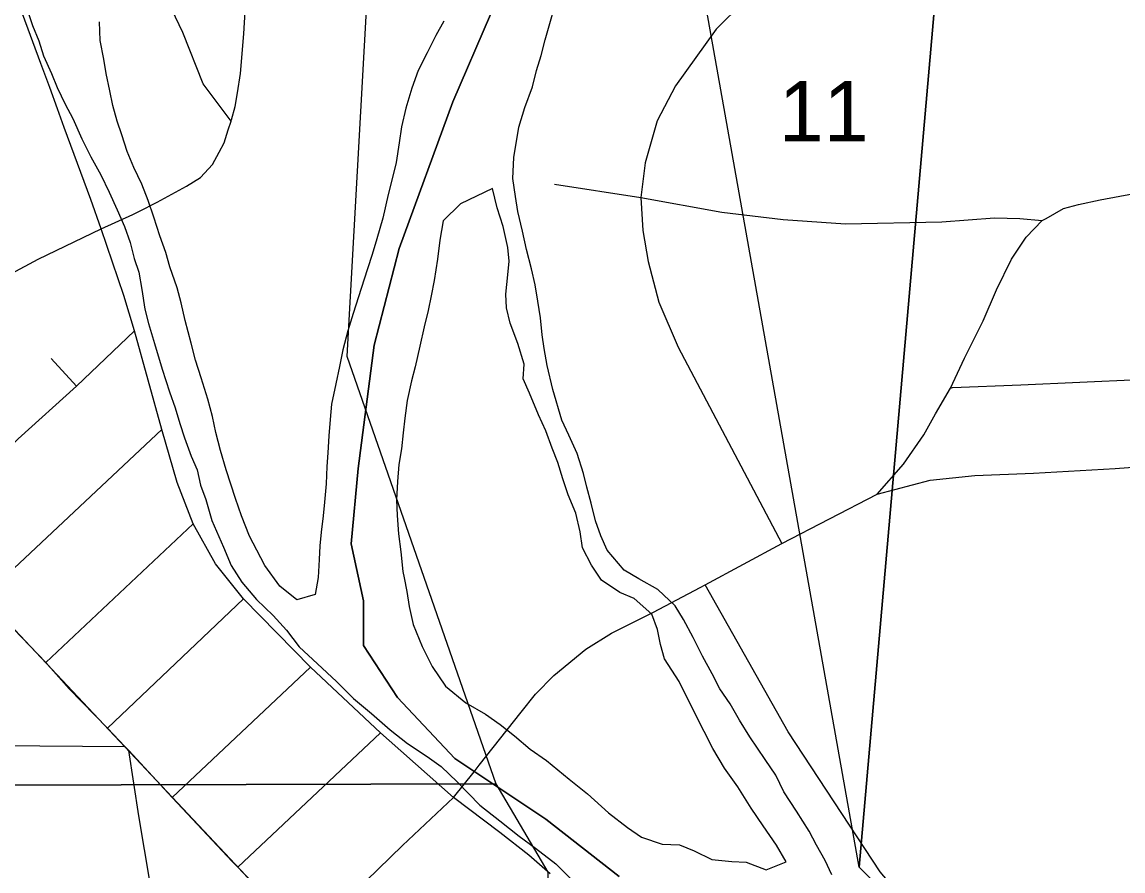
# Model space of a CAD drawing. Extents: x 0 to 34, y 0 to 22.
# Drawn here: x 5.661 to 6.424, y 19.444 to 20.032 of the extents above; entities that cross this region are included whole.
import ezdxf

# ---------------------------------------------------------------- set-up
doc = ezdxf.new("R2010")
doc.units = 0
for name, color, linetype in [('GM_X_City_Street', 7, 'Continuous'), ('GM_X_County_Road', 7, 'Continuous'), ('GM_X_Major_River', 7, 'Continuous'), ('GM_X_Rail_Line', 7, 'Continuous'), ('GM_X_Section', 7, 'Continuous'), ('GM_X_Section_Text', 7, 'Continuous'), ('GM_X_State_Route', 7, 'Continuous'), ('GM_X_Township_Road', 7, 'Continuous')]:
    doc.layers.add(name, color=color, linetype=linetype)

msp = doc.modelspace()

# ---------------------------------------------------------------- linework, layer by layer
at = {"layer": 'GM_X_City_Street'}
for p, q in [((5.69908, 19.77954), (5.68137, 19.79885)), ((5.63415, 19.63335), (5.75809, 19.7495)), ((5.67771, 19.58808), (5.77993, 19.68429)), ((5.72049, 19.54272), (5.81472, 19.63218)), ((5.76529, 19.49469), (5.86126, 19.58503)), ((5.81082, 19.44626), (5.9096, 19.5394)), ((5.61432, 19.53093), (5.73258, 19.52994))]:
    msp.add_line(p, q, dxfattribs=at)
for points in [[(5.80628, 19.96327), (5.7868, 19.98904), (5.77257, 20.0246), (5.76261, 20.04594), (5.75692, 20.10143), (5.74554, 20.16545), (5.73985, 20.20102), (5.73416, 20.24654), (5.72705, 20.2878), (5.71851, 20.31625), (5.71424, 20.33759), (5.71282, 20.36462), (5.70855, 20.3945), (5.70589, 20.45235), (5.70855, 20.49754), (5.71096, 20.56277), (5.70911, 20.59297), (5.70541, 20.65399), (5.70082, 20.69532), (5.69167, 20.73859), (5.659, 20.86529), (5.65113, 20.89381), (5.64998, 20.9)], [(6.48949, 20.17565), (6.41974, 20.16506), (6.34311, 20.1509), (6.31729, 20.1434), (6.2798, 20.12841), (6.24316, 20.10925), (6.21817, 20.09426), (6.18652, 20.07011), (6.16153, 20.04595), (6.14238, 20.02679), (6.11405, 19.98764), (6.10156, 19.96349), (6.09323, 19.93434), (6.09013, 19.9103), (6.0916, 19.88736), (6.09531, 19.86589), (6.10271, 19.83776), (6.11603, 19.80667), (6.18784, 19.67065)], [(6.03036, 19.91953), (6.09013, 19.9103), (6.14638, 19.90019), (6.18877, 19.89499), (6.23192, 19.89201), (6.29885, 19.8935), (6.33529, 19.8961), (6.35277, 19.89573), (6.36839, 19.89424)], [(6.36839, 19.89424), (6.37099, 19.89572), (6.38316, 19.90263), (6.39345, 19.90539), (6.40852, 19.90865), (6.44191, 19.91493), (6.48534, 19.92372)], [(6.25386, 19.70479), (6.27219, 19.72563), (6.28625, 19.74596), (6.29428, 19.76053), (6.30483, 19.7781), (6.31437, 19.79894), (6.32743, 19.8248), (6.33672, 19.84639), (6.34701, 19.86748), (6.3573, 19.88279), (6.36839, 19.89424)], [(6.30483, 19.7781), (6.30607, 19.77873), (6.35351, 19.78041), (6.43536, 19.78418), (6.45131, 19.7867), (6.46223, 19.78964), (6.49539, 19.81021), (6.52205, 19.82757), (6.55206, 19.84886), (6.55666, 19.85203), (6.56012, 19.85347), (6.56386, 19.85462), (6.56905, 19.85434), (6.62982, 19.84818)], [(5.59105, 19.67895), (5.65852, 19.74307), (5.69908, 19.77954), (5.73926, 19.81788)], [(6.13129, 19.64007), (6.13478, 19.64191), (6.18784, 19.67065), (6.25386, 19.70479), (6.29077, 19.71458), (6.32165, 19.71759), (6.36232, 19.71935), (6.41899, 19.72261), (6.47135, 19.72658), (6.5006, 19.732), (6.53022, 19.74175), (6.56901, 19.75773)], [(5.96036, 19.49467), (5.97456, 19.51243), (5.97817, 19.51696), (6.00714, 19.55378), (6.0172, 19.56613), (6.02983, 19.57906), (6.05208, 19.59741), (6.06983, 19.60853), (6.09899, 19.62296), (6.13129, 19.64007)], [(6.43618, 19.23919), (6.37806, 19.30501), (6.29517, 19.3971), (6.25603, 19.44315), (6.19214, 19.54014), (6.13478, 19.64191)], [(5.8027, 19.10411), (5.79262, 19.16742), (5.78376, 19.22821), (5.76781, 19.32468), (5.76345, 19.35451), (5.75786, 19.38657), (5.75002, 19.43534), (5.74218, 19.48194), (5.73519, 19.52725)], [(5.8573, 19.39686), (5.89119, 19.4287), (5.92487, 19.46147), (5.96036, 19.49467)]]:
    msp.add_lwpolyline(points, dxfattribs=at)
at = {"layer": 'GM_X_County_Road'}
msp.add_line((5.96036, 19.49467), (5.91558, 19.53414), dxfattribs=at)
for points in [[(5.68583, 19.97163), (5.68052, 19.98641), (5.67435, 20.00313), (5.66155, 20.03747), (5.65481, 20.05838)], [(5.716, 19.88847), (5.70884, 19.909), (5.69047, 19.9587), (5.68583, 19.97163)], [(5.91558, 19.53414), (5.9096, 19.5394), (5.86126, 19.58503), (5.81472, 19.63218), (5.79529, 19.65642), (5.77993, 19.68429), (5.76872, 19.71285), (5.75809, 19.7495), (5.73926, 19.81788), (5.73189, 19.8424), (5.716, 19.88847)], [(6.02723, 19.44165), (6.01247, 19.45461), (5.99244, 19.47027), (5.96036, 19.49467)]]:
    msp.add_lwpolyline(points, dxfattribs=at)
at = {"layer": 'GM_X_Major_River'}
for points in [[(5.66388, 20.04321), (5.66855, 20.02943), (5.67289, 20.01871), (5.67611, 20.00838), (5.68157, 19.99611), (5.68556, 19.98653), (5.69103, 19.97502), (5.69653, 19.96503), (5.70271, 19.95084), (5.70892, 19.93856), (5.71589, 19.92588), (5.72173, 19.91398), (5.72719, 19.90171), (5.73228, 19.89021), (5.73624, 19.8791), (5.73906, 19.86803), (5.74229, 19.85846), (5.74434, 19.84664), (5.74635, 19.83292), (5.74881, 19.823), (5.7531, 19.80923), (5.75844, 19.79126), (5.76345, 19.77558), (5.76741, 19.76448), (5.77062, 19.75378), (5.77384, 19.74383), (5.77853, 19.7312), (5.78252, 19.72162), (5.78497, 19.71093), (5.78857, 19.70098), (5.79284, 19.68645), (5.80084, 19.66805), (5.80629, 19.6554), (5.81366, 19.64385), (5.82368, 19.63187), (5.83523, 19.62062), (5.84453, 19.61055), (5.85342, 19.59897), (5.8661, 19.58731), (5.87916, 19.57489), (5.89108, 19.56324), (5.90341, 19.55273), (5.91649, 19.54145), (5.92846, 19.53208), (5.94196, 19.52307), (5.9517, 19.51603)], [(5.87476, 19.7566), (5.87378, 19.74521), (5.87317, 19.73345), (5.8726, 19.72396), (5.87198, 19.71182), (5.87097, 19.6993), (5.87003, 19.68982), (5.86866, 19.67845), (5.86772, 19.66897), (5.86715, 19.65948), (5.86652, 19.64696), (5.86439, 19.63522), (5.85179, 19.63168), (5.83982, 19.64104), (5.82946, 19.65531), (5.82397, 19.66606), (5.81884, 19.67566), (5.81342, 19.68983), (5.8091, 19.7017), (5.80588, 19.71164), (5.80265, 19.72159), (5.79874, 19.73497), (5.79557, 19.74757), (5.79313, 19.75864), (5.78994, 19.77048), (5.7853, 19.78539), (5.78136, 19.79764), (5.77855, 19.80947), (5.7743, 19.82514), (5.77151, 19.83735), (5.76867, 19.84767), (5.76364, 19.86221), (5.7608, 19.87215), (5.75684, 19.88363), (5.75254, 19.89663), (5.74859, 19.90811), (5.74426, 19.9196), (5.73879, 19.93111), (5.73407, 19.94223), (5.7305, 19.9537), (5.72727, 19.96326), (5.72406, 19.97397), (5.72198, 19.98427), (5.71955, 19.9961), (5.71785, 20.00601), (5.71545, 20.01898), (5.71494, 20.03191)], [(5.95352, 20.03237), (5.94801, 20.0226), (5.94207, 20.01057), (5.93575, 19.99816), (5.93133, 19.98609), (5.92726, 19.97211), (5.92435, 19.95925), (5.92261, 19.94826), (5.92044, 19.93463), (5.91796, 19.92404), (5.91506, 19.91232), (5.91132, 19.89606), (5.90724, 19.8817), (5.90399, 19.87075), (5.90075, 19.86094), (5.89631, 19.84735), (5.89065, 19.82999), (5.88699, 19.8179), (5.88369, 19.80467), (5.88119, 19.79332), (5.87867, 19.78121), (5.87573, 19.76721), (5.87476, 19.7566)], [(6.18369, 19.51014), (6.17631, 19.52093), (6.1656, 19.53673), (6.15861, 19.54827), (6.15199, 19.55942), (6.14498, 19.56983), (6.13949, 19.5802), (6.13289, 19.59249), (6.12631, 19.60555), (6.11971, 19.61784), (6.11383, 19.62746), (6.10189, 19.63872), (6.08874, 19.64621), (6.0786, 19.65212), (6.06672, 19.66604), (6.06236, 19.67601), (6.05876, 19.68634), (6.05559, 19.69857), (6.05277, 19.70964), (6.05029, 19.71919), (6.04601, 19.73296), (6.04018, 19.74562), (6.03544, 19.75597), (6.02903, 19.77738), (6.02517, 19.7938), (6.02313, 19.80562), (6.02179, 19.81515), (6.02051, 19.82695), (6.01883, 19.83839), (6.01678, 19.84983), (6.01434, 19.8609), (6.01081, 19.87427), (6.00802, 19.88686), (6.00487, 19.90061), (6.00317, 19.9109), (6.00152, 19.92348), (6.00218, 19.9379), (6.00564, 19.95911), (6.00971, 19.97271), (6.01493, 19.98704), (6.01781, 19.99838), (6.02105, 20.00857), (6.02393, 20.01953), (6.02884, 20.03729)], [(5.98733, 19.91655), (5.96508, 19.90598), (5.95307, 19.89407), (5.95091, 19.88081), (5.94913, 19.86755), (5.94694, 19.85277), (5.94483, 19.84218), (5.94273, 19.83196), (5.93985, 19.82062), (5.93693, 19.80738), (5.9336, 19.79301), (5.93113, 19.78318), (5.9282, 19.76956), (5.92645, 19.75744), (5.92548, 19.7472), (5.92413, 19.73621), (5.92239, 19.72523), (5.9214, 19.71347), (5.92077, 19.70094), (5.92131, 19.68991), (5.92221, 19.67735), (5.92386, 19.66478), (5.92511, 19.65108), (5.92616, 19.64688)], [(5.92616, 19.64688), (5.92788, 19.63734), (5.92957, 19.62705), (5.93236, 19.61446), (5.93852, 19.59913), (5.94546, 19.58531), (5.95469, 19.57182), (5.9689, 19.56014), (5.98242, 19.55226), (5.99254, 19.54521), (6.00264, 19.53741), (6.01347, 19.52807), (6.02472, 19.52024), (6.04042, 19.50738), (6.05314, 19.49724), (6.06769, 19.48402), (6.08079, 19.47388), (6.09053, 19.46722), (6.10487, 19.46236), (6.11702, 19.46173), (6.1272, 19.45773), (6.13923, 19.45178), (6.15326, 19.45035), (6.16313, 19.44977), (6.17708, 19.44454), (6.19086, 19.44996), (6.18425, 19.4615), (6.17502, 19.47498), (6.16653, 19.48732), (6.15732, 19.50194), (6.14808, 19.51505), (6.13999, 19.52851), (6.13414, 19.54041), (6.1239, 19.56038), (6.11659, 19.57497), (6.10664, 19.59075), (6.1038, 19.60069), (6.10172, 19.61099), (6.09776, 19.62171), (6.08544, 19.6326), (6.07564, 19.6366), (6.06289, 19.64522), (6.05588, 19.65562), (6.04965, 19.66753), (6.04797, 19.67858), (6.04519, 19.69156), (6.03974, 19.70421), (6.03616, 19.7153), (6.03259, 19.72677), (6.0286, 19.73673), (6.02428, 19.7486), (6.01918, 19.75972), (6.01302, 19.77467), (6.00866, 19.78464), (6.00924, 19.79489), (6.00496, 19.80903), (5.99954, 19.8232), (5.99709, 19.83389), (5.99652, 19.8434), (5.99792, 19.85667), (5.99887, 19.86615), (5.99792, 19.87567), (5.99478, 19.89017), (5.99048, 19.90318), (5.98733, 19.91655)], [(5.9517, 19.51603), (5.96289, 19.50554), (5.97852, 19.48927), (5.99236, 19.47835), (6.00583, 19.46781), (6.01706, 19.4596), (6.03128, 19.44867), (6.04395, 19.43588)], [(6.2226, 19.44095), (6.21785, 19.45092), (6.21199, 19.46168), (6.20686, 19.47129), (6.19802, 19.48515), (6.18916, 19.49863), (6.18369, 19.51014)]]:
    msp.add_lwpolyline(points, dxfattribs=at)
at = {"layer": 'GM_X_Rail_Line'}
msp.add_lwpolyline([(5.34106, 20.06734), (5.47047, 19.808), (5.93994, 19.30918), (6.13609, 19.10059), (6.1472, 19.0806), (6.24546, 18.59231)], dxfattribs=at)
at = {"layer": 'GM_X_Section'}
for points in [[(5.03178, 20.49467), (6.02623, 20.49008), (6.02727, 20.20147), (5.90073, 20.05689), (5.88646, 19.80039), (5.98962, 19.50419), (5.03707, 19.50155)], [(6.12431, 20.1046), (6.29786, 20.08961), (6.24153, 19.44646)], [(6.29786, 20.08961), (7.29266, 20.00283), (7.19193, 18.99089), (6.64905, 19.04232), (6.24153, 19.44646)], [(5.98962, 19.50419), (6.02559, 19.44292), (6.02539, 18.74343), (5.61791, 18.48139), (5.03965, 18.48463), (5.03707, 19.50155)]]:
    msp.add_lwpolyline(points, close=True, dxfattribs=at)
at = {"layer": 'GM_X_State_Route'}
for points in [[(5.80721, 19.45011), (5.76529, 19.49469), (5.73519, 19.52725), (5.73258, 19.52994), (5.72049, 19.54272), (5.69398, 19.57), (5.67771, 19.58808), (5.63871, 19.62865), (5.63415, 19.63335), (5.59105, 19.67895), (5.56481, 19.70708), (5.52674, 19.74683), (5.51377, 19.7619)], [(5.88384, 19.3685), (5.87818, 19.37467), (5.8573, 19.39686), (5.81082, 19.44626), (5.80721, 19.45011)]]:
    msp.add_lwpolyline(points, dxfattribs=at)
at = {"layer": 'GM_X_Township_Road'}
for points in [[(5.81046, 19.9829), (5.81267, 19.99614), (5.81495, 20.02358), (5.81723, 20.06246)], [(6.07513, 19.43999), (6.02432, 19.47964), (5.97432, 19.51297), (5.96112, 19.52176), (5.92146, 19.56389), (5.89791, 19.59982), (5.89791, 19.63079), (5.88924, 19.67044), (5.8942, 19.72247), (5.90535, 19.80795), (5.9227, 19.87486), (5.95987, 19.97645), (5.98589, 20.03717)], [(5.98589, 20.03717), (5.95987, 19.97645), (5.9227, 19.87486), (5.90535, 19.80795), (5.8942, 19.72247), (5.88924, 19.67044), (5.89791, 19.63079), (5.89791, 19.59982), (5.92146, 19.56389), (5.96112, 19.52176), (5.97432, 19.51297), (6.02432, 19.47964), (6.07513, 19.43999)], [(5.80651, 19.96419), (5.80887, 19.97343), (5.81046, 19.9829)], [(5.74221, 19.90059), (5.75491, 19.9071), (5.77531, 19.91818), (5.78486, 19.92425), (5.79332, 19.93315), (5.79787, 19.94176), (5.80123, 19.94812), (5.80421, 19.95708), (5.80628, 19.96327), (5.80651, 19.96419)], [(5.716, 19.88847), (5.73798, 19.89842), (5.74221, 19.90059)], [(5.52674, 19.74683), (5.59517, 19.81031), (5.60908, 19.82338), (5.6312, 19.84416), (5.63815, 19.84938), (5.67243, 19.86761), (5.716, 19.88847)]]:
    msp.add_lwpolyline(points, dxfattribs=at)

# ---------------------------------------------------------------- texts
at = {"layer": 'GM_X_Section_Text'}
msp.add_text('11', height=0.041856, rotation=0.00001, dxfattribs=at).set_placement((6.18577, 19.94908))

doc.saveas('drawing.dxf')
